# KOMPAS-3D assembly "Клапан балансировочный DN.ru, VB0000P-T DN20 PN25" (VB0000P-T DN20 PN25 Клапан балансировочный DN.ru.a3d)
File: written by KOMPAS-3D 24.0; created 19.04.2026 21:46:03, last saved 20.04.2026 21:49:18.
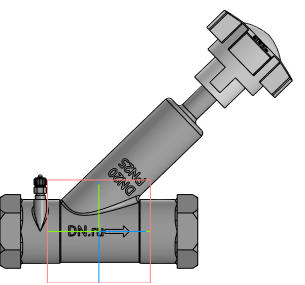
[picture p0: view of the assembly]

Document properties: Автор: DN.ru; Полное имя файла: C:\Работа\VB0000P-T DN X PN 25 Клапан балансировочный DN.ru\DN20\исходные материалы\VB0000P-T DN20 PN25 Клапан балансировочный DN.ru.a3d

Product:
- Component [detail]: Деталь  | qty 1  | pos. 1  | Масса: 0.513247; Автор: mrdid; source file: VB0000P-T DN20 PN25 Клапан балансировочный DN.ru.m3d
- Component [detail]: Деталь2  | qty 1  | pos. 2  | Масса: 0.240364; Автор: tyuri; additional columns: Типовые; source file: Деталь2 - Деталь2.m3d
- Part/product: Клапан балансировочный DN.ru  | designation VB0000P-T DN20 PN25
    Масса: 0.58
    Раздел спецификации: Прочие изделия
    Примечание: D080-01176

Referenced files in C:\Работа\VB0000P-T DN X PN 25 Клапан балансировочный DN.ru\DN20\исходные материалы\: Деталь2 - Деталь2.m3d, VB0000P-T DN20 PN25 Клапан балансировочный DN.ru.m3d
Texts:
  VB0000P-T DN20 PN25
  Деталь2 Деталь2
  Плоскость XY.Начало координат
  Плоскость ZY.Начало координат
